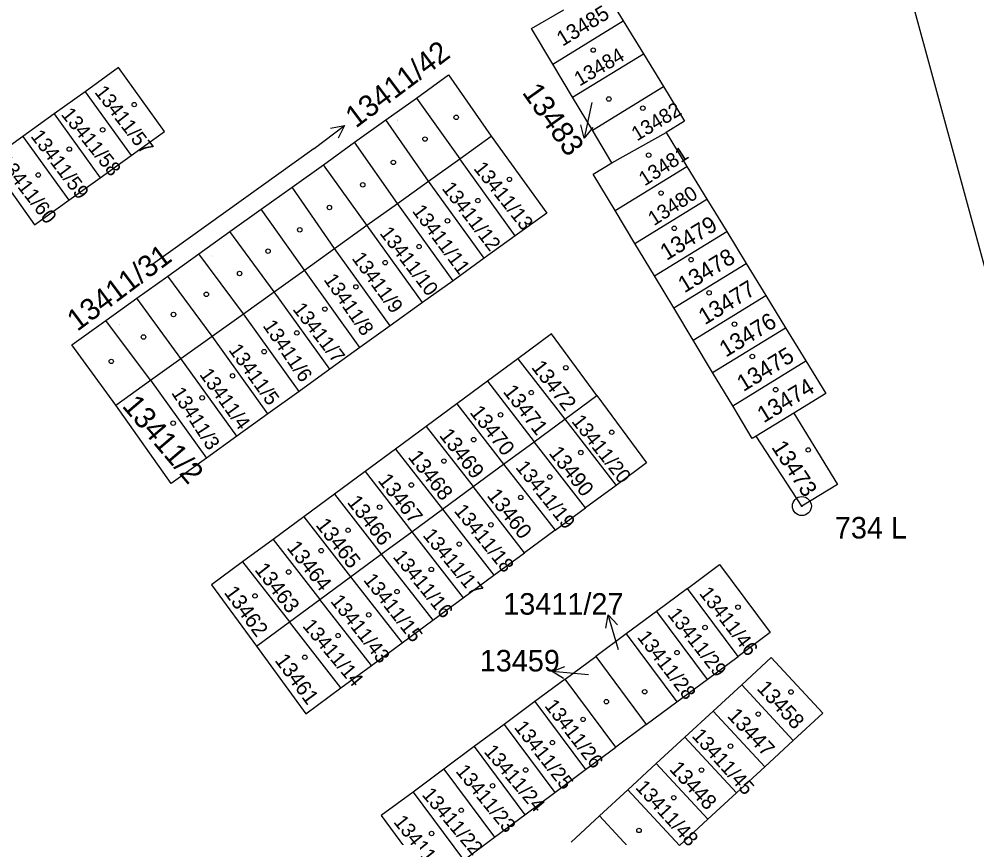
# Model space of a CAD drawing. Extents: x -822293 to -820259, y -1071573 to -1068794.
# Drawn here: x -820673 to -820597.4, y -1071103.6 to -1071039 of the extents above; entities that cross this region are included whole.
import ezdxf

# ---------------------------------------------------------------- set-up
doc = ezdxf.new("R2010")
doc.units = 0
for name, color, linetype in [('Vrstva 1', 7, 'Continuous'), ('Vrstva 16', 7, 'Continuous'), ('Vrstva 17', 7, 'Continuous'), ('Vrstva 19', 7, 'Continuous'), ('Vrstva 2', 7, 'Continuous'), ('Vrstva 24', 7, 'Continuous'), ('Vrstva 25', 7, 'Continuous')]:
    doc.layers.add(name, color=color, linetype=linetype)

msp = doc.modelspace()

# ---------------------------------------------------------------- linework, layer by layer
at = {"layer": 'Vrstva 1'}
msp.add_line((-820596.7, -1071059), (-820638.53, -1070906.11), dxfattribs=at)
at = {"layer": 'Vrstva 16'}
for p, q in [((-820627.8, -1071045.6), (-820628.42, -1071048.43)), ((-820649.71, -1071049.23), (-820647.314, -1071047.424)), ((-820649.71, -1071049.23), (-820662.44, -1071058.37)), ((-820625.7, -1071088.8), (-820626.52, -1071086.02)), ((-820628.07, -1071090.76), (-820630.95, -1071090.5))]:
    msp.add_line(p, q, dxfattribs=at)
for points in [[(-820648.414, -1071047.627), (-820647.314, -1071047.424), (-820647.812, -1071048.425)], [(-820627.742, -1071047.59), (-820628.42, -1071048.43), (-820628.685, -1071047.383)], [(-820626.71, -1071087.083), (-820626.52, -1071086.02), (-820625.783, -1071086.81)], [(-820630.033, -1071091.067), (-820630.95, -1071090.5), (-820629.947, -1071090.107)]]:
    msp.add_lwpolyline(points, dxfattribs=at)
at = {"layer": 'Vrstva 2'}
for p, q in [((-820626.88, -1071036.63), (-820625.33, -1071039.17)), ((-820632.58, -1071039.77), (-820630.01, -1071038.31)), ((-820630.9, -1071042.58), (-820632.58, -1071039.77)), ((-820630.9, -1071042.58), (-820625.33, -1071039.17)), ((-820625.33, -1071039.17), (-820623.74, -1071041.77)), ((-820629.33, -1071045.19), (-820623.74, -1071041.77)), ((-820623.74, -1071041.77), (-820622.15, -1071044.36)), ((-820665.15, -1071042.86), (-820667.79, -1071044.76)), ((-820661.52, -1071047.91), (-820665.15, -1071042.86)), ((-820629.33, -1071045.19), (-820630.9, -1071042.58)), ((-820641.65, -1071045.26), (-820639.12, -1071043.44)), ((-820639.12, -1071043.44), (-820635.75, -1071048.27)), ((-820627.77, -1071047.8), (-820622.15, -1071044.36)), ((-820622.15, -1071044.36), (-820620.49, -1071047.08)), ((-820667.79, -1071044.76), (-820670.23, -1071046.52)), ((-820667.79, -1071044.76), (-820664.16, -1071049.8)), ((-820644.06, -1071046.98), (-820641.65, -1071045.26)), ((-820641.65, -1071045.26), (-820638.22, -1071050.05)), ((-820627.77, -1071047.8), (-820629.33, -1071045.19)), ((-820670.23, -1071046.52), (-820672.7, -1071048.29)), ((-820670.23, -1071046.52), (-820666.6, -1071051.55)), ((-820646.53, -1071048.75), (-820644.06, -1071046.98)), ((-820640.69, -1071051.81), (-820644.06, -1071046.98)), ((-820620.49, -1071047.08), (-820621.95, -1071047.97)), ((-820664.16, -1071049.8), (-820661.52, -1071047.91)), ((-820626.23, -1071050.37), (-820627.77, -1071047.8)), ((-820626.23, -1071050.37), (-820621.95, -1071047.97)), ((-820621.95, -1071047.97), (-820620.31, -1071050.66)), ((-820672.7, -1071048.29), (-820675.36, -1071050.21)), ((-820672.7, -1071048.29), (-820669.07, -1071053.32)), ((-820648.99, -1071050.52), (-820646.53, -1071048.75)), ((-820643.15, -1071053.58), (-820646.53, -1071048.75)), ((-820638.22, -1071050.05), (-820635.75, -1071048.27)), ((-820635.75, -1071048.27), (-820631.36, -1071054.34)), ((-820675.36, -1071050.21), (-820671.77, -1071055.26)), ((-820666.6, -1071051.55), (-820664.16, -1071049.8)), ((-820640.69, -1071051.81), (-820638.22, -1071050.05)), ((-820633.85, -1071056.13), (-820638.22, -1071050.05)), ((-820627.7, -1071051.26), (-820626.23, -1071050.37)), ((-820651.45, -1071052.28), (-820648.99, -1071050.52)), ((-820645.55, -1071055.3), (-820648.99, -1071050.52)), ((-820625.97, -1071054.13), (-820620.31, -1071050.66)), ((-820620.31, -1071050.66), (-820618.73, -1071053.25)), ((-820669.07, -1071053.32), (-820666.6, -1071051.55)), ((-820643.15, -1071053.58), (-820640.69, -1071051.81)), ((-820636.31, -1071057.9), (-820640.69, -1071051.81)), ((-820625.97, -1071054.13), (-820627.7, -1071051.26)), ((-820653.9, -1071054.04), (-820651.45, -1071052.28)), ((-820648.11, -1071057.12), (-820651.45, -1071052.28)), ((-820671.77, -1071055.26), (-820669.07, -1071053.32)), ((-820624.41, -1071056.73), (-820618.73, -1071053.25)), ((-820618.73, -1071053.25), (-820617.17, -1071055.79)), ((-820656.36, -1071055.8), (-820653.9, -1071054.04)), ((-820650.49, -1071058.83), (-820653.9, -1071054.04)), ((-820645.55, -1071055.3), (-820643.15, -1071053.58)), ((-820638.76, -1071059.67), (-820643.15, -1071053.58)), ((-820624.41, -1071056.73), (-820625.97, -1071054.13)), ((-820631.36, -1071054.34), (-820633.85, -1071056.13)), ((-820648.11, -1071057.12), (-820645.55, -1071055.3)), ((-820641.16, -1071061.39), (-820645.55, -1071055.3)), ((-820658.82, -1071057.56), (-820656.36, -1071055.8)), ((-820652.87, -1071060.54), (-820656.36, -1071055.8)), ((-820633.85, -1071056.13), (-820636.31, -1071057.9)), ((-820622.87, -1071059.28), (-820617.17, -1071055.79)), ((-820617.17, -1071055.79), (-820615.63, -1071058.31)), ((-820650.49, -1071058.83), (-820648.11, -1071057.12)), ((-820643.71, -1071063.22), (-820648.11, -1071057.12)), ((-820622.87, -1071059.28), (-820624.41, -1071056.73)), ((-820661.27, -1071059.32), (-820658.82, -1071057.56)), ((-820655.3, -1071062.28), (-820658.82, -1071057.56)), ((-820636.31, -1071057.9), (-820638.76, -1071059.67)), ((-820621.35, -1071061.81), (-820615.63, -1071058.31)), ((-820615.63, -1071058.31), (-820614.08, -1071060.84)), ((-820663.71, -1071061.06), (-820661.27, -1071059.32)), ((-820657.77, -1071064.05), (-820661.27, -1071059.32)), ((-820652.87, -1071060.54), (-820650.49, -1071058.83)), ((-820646.1, -1071064.94), (-820650.49, -1071058.83)), ((-820621.35, -1071061.81), (-820622.87, -1071059.28)), ((-820638.76, -1071059.67), (-820641.16, -1071061.39)), ((-820655.3, -1071062.28), (-820652.87, -1071060.54)), ((-820648.49, -1071066.66), (-820652.87, -1071060.54)), ((-820619.82, -1071064.35), (-820614.08, -1071060.84)), ((-820614.08, -1071060.84), (-820612.53, -1071063.38)), ((-820666.16, -1071062.82), (-820663.71, -1071061.06)), ((-820660.23, -1071065.81), (-820663.71, -1071061.06)), ((-820641.16, -1071061.39), (-820643.71, -1071063.22)), ((-820657.77, -1071064.05), (-820655.3, -1071062.28)), ((-820650.9, -1071068.4), (-820655.3, -1071062.28)), ((-820619.82, -1071064.35), (-820621.35, -1071061.81)), ((-820668.84, -1071064.74), (-820666.16, -1071062.82)), ((-820662.63, -1071067.53), (-820666.16, -1071062.82)), ((-820643.71, -1071063.22), (-820646.1, -1071064.94)), ((-820660.23, -1071065.81), (-820657.77, -1071064.05)), ((-820653.36, -1071070.17), (-820657.77, -1071064.05)), ((-820630.98, -1071063.87), (-820633.64, -1071065.84)), ((-820627.41, -1071068.72), (-820630.98, -1071063.87)), ((-820618.29, -1071066.91), (-820612.53, -1071063.38)), ((-820612.53, -1071063.38), (-820610.92, -1071066)), ((-820665.36, -1071069.48), (-820668.84, -1071064.74)), ((-820618.29, -1071066.91), (-820619.82, -1071064.35)), ((-820646.1, -1071064.94), (-820648.49, -1071066.66)), ((-820662.63, -1071067.53), (-820660.23, -1071065.81)), ((-820655.82, -1071071.94), (-820660.23, -1071065.81)), ((-820633.64, -1071065.84), (-820636.05, -1071067.61)), ((-820633.64, -1071065.84), (-820629.95, -1071070.59)), ((-820616.7, -1071069.54), (-820610.92, -1071066)), ((-820610.92, -1071066), (-820609.35, -1071068.57)), ((-820648.49, -1071066.66), (-820650.9, -1071068.4)), ((-820616.7, -1071069.54), (-820618.29, -1071066.91)), ((-820665.36, -1071069.48), (-820662.63, -1071067.53)), ((-820662.63, -1071067.53), (-820658.21, -1071073.66)), ((-820636.05, -1071067.61), (-820638.46, -1071069.39)), ((-820636.05, -1071067.61), (-820632.36, -1071072.37)), ((-820650.9, -1071068.4), (-820653.36, -1071070.17)), ((-820609.35, -1071068.57), (-820611.88, -1071070.12)), ((-820629.95, -1071070.59), (-820627.41, -1071068.72)), ((-820627.41, -1071068.72), (-820623.49, -1071074.05)), ((-820660.99, -1071075.66), (-820665.36, -1071069.48)), ((-820638.46, -1071069.39), (-820640.88, -1071071.17)), ((-820638.46, -1071069.39), (-820634.77, -1071074.14)), ((-820615.15, -1071072.12), (-820616.7, -1071069.54)), ((-820653.36, -1071070.17), (-820655.82, -1071071.94)), ((-820632.36, -1071072.37), (-820629.95, -1071070.59)), ((-820629.95, -1071070.59), (-820625.89, -1071075.82)), ((-820611.88, -1071070.12), (-820614.84, -1071071.94)), ((-820611.88, -1071070.12), (-820608.44, -1071075.74)), ((-820640.88, -1071071.17), (-820643.29, -1071072.95)), ((-820640.88, -1071071.17), (-820637.18, -1071075.92)), ((-820655.82, -1071071.94), (-820658.21, -1071073.66)), ((-820634.77, -1071074.14), (-820632.36, -1071072.37)), ((-820628.3, -1071077.59), (-820632.36, -1071072.37)), ((-820614.84, -1071071.94), (-820615.15, -1071072.12)), ((-820611.24, -1071077.45), (-820614.84, -1071071.94)), ((-820643.29, -1071072.95), (-820645.7, -1071074.73)), ((-820643.29, -1071072.95), (-820639.59, -1071077.7)), ((-820658.21, -1071073.66), (-820660.99, -1071075.66)), ((-820637.18, -1071075.92), (-820634.77, -1071074.14)), ((-820634.77, -1071074.14), (-820630.7, -1071079.36)), ((-820623.49, -1071074.05), (-820625.89, -1071075.82)), ((-820645.7, -1071074.73), (-820648.12, -1071076.51)), ((-820645.7, -1071074.73), (-820642.02, -1071079.48)), ((-820639.59, -1071077.7), (-820637.18, -1071075.92)), ((-820633.11, -1071081.13), (-820637.18, -1071075.92)), ((-820625.89, -1071075.82), (-820628.3, -1071077.59)), ((-820608.44, -1071075.74), (-820611.24, -1071077.45)), ((-820648.12, -1071076.51), (-820650.53, -1071078.3)), ((-820648.12, -1071076.51), (-820644.42, -1071081.25)), ((-820630.7, -1071079.36), (-820628.3, -1071077.59)), ((-820650.53, -1071078.3), (-820652.95, -1071080.08)), ((-820650.53, -1071078.3), (-820646.84, -1071083.03)), ((-820642.02, -1071079.48), (-820639.59, -1071077.7)), ((-820639.59, -1071077.7), (-820635.53, -1071082.91)), ((-820644.42, -1071081.25), (-820642.02, -1071079.48)), ((-820642.02, -1071079.48), (-820637.96, -1071084.7)), ((-820630.7, -1071079.36), (-820633.11, -1071081.13)), ((-820652.95, -1071080.08), (-820655.36, -1071081.86)), ((-820652.95, -1071080.08), (-820649.26, -1071084.81)), ((-820646.84, -1071083.03), (-820644.42, -1071081.25)), ((-820644.42, -1071081.25), (-820640.35, -1071086.46)), ((-820635.53, -1071082.91), (-820633.11, -1071081.13)), ((-820655.36, -1071081.86), (-820657.82, -1071083.67)), ((-820655.36, -1071081.86), (-820651.67, -1071086.59)), ((-820620.27, -1071083.95), (-820617.73, -1071082.07)), ((-820617.73, -1071082.07), (-820613.74, -1071087.42)), ((-820637.96, -1071084.7), (-820635.53, -1071082.91)), ((-820657.82, -1071083.67), (-820654.27, -1071088.51)), ((-820649.26, -1071084.81), (-820646.84, -1071083.03)), ((-820646.84, -1071083.03), (-820642.78, -1071088.25)), ((-820620.27, -1071083.95), (-820622.71, -1071085.76)), ((-820616.28, -1071089.31), (-820620.27, -1071083.95)), ((-820651.67, -1071086.59), (-820649.26, -1071084.81)), ((-820645.19, -1071090.02), (-820649.26, -1071084.81)), ((-820640.35, -1071086.46), (-820637.96, -1071084.7)), ((-820622.71, -1071085.76), (-820625.09, -1071087.53)), ((-820622.71, -1071085.76), (-820618.72, -1071091.13)), ((-820654.27, -1071088.51), (-820651.67, -1071086.59)), ((-820647.61, -1071091.8), (-820651.67, -1071086.59)), ((-820642.78, -1071088.25), (-820640.35, -1071086.46)), ((-820613.74, -1071087.42), (-820616.28, -1071089.31)), ((-820625.09, -1071087.53), (-820627.5, -1071089.32)), ((-820625.09, -1071087.53), (-820621.11, -1071092.9)), ((-820654.27, -1071088.51), (-820650.36, -1071093.83)), ((-820645.19, -1071090.02), (-820642.78, -1071088.25)), ((-820629.91, -1071091.1), (-820627.5, -1071089.32)), ((-820627.5, -1071089.32), (-820623.52, -1071094.68)), ((-820618.72, -1071091.13), (-820616.28, -1071089.31)), ((-820615.99, -1071091.55), (-820613.67, -1071089.41)), ((-820613.67, -1071089.41), (-820609.6, -1071093.8)), ((-820647.61, -1071091.8), (-820645.19, -1071090.02)), ((-820629.91, -1071091.1), (-820632.3, -1071092.87)), ((-820625.93, -1071096.47), (-820629.91, -1071091.1)), ((-820621.11, -1071092.9), (-820618.72, -1071091.13)), ((-820650.36, -1071093.83), (-820647.61, -1071091.8)), ((-820618.24, -1071093.62), (-820615.99, -1071091.55)), ((-820615.99, -1071091.55), (-820611.92, -1071095.94)), ((-820632.3, -1071092.87), (-820634.72, -1071094.67)), ((-820632.3, -1071092.87), (-820628.31, -1071098.24)), ((-820623.52, -1071094.68), (-820621.11, -1071092.9)), ((-820620.47, -1071095.69), (-820618.24, -1071093.62)), ((-820614.17, -1071098.01), (-820618.24, -1071093.62)), ((-820609.6, -1071093.8), (-820611.92, -1071095.94)), ((-820634.72, -1071094.67), (-820637.09, -1071096.43)), ((-820634.72, -1071094.67), (-820630.73, -1071100.04)), ((-820623.52, -1071094.68), (-820625.93, -1071096.47)), ((-820622.74, -1071097.77), (-820620.47, -1071095.69)), ((-820620.47, -1071095.69), (-820616.4, -1071100.07)), ((-820637.09, -1071096.43), (-820639.49, -1071098.21)), ((-820637.09, -1071096.43), (-820633.1, -1071101.8)), ((-820628.31, -1071098.24), (-820625.93, -1071096.47)), ((-820611.92, -1071095.94), (-820614.17, -1071098.01)), ((-820624.97, -1071099.83), (-820622.74, -1071097.77)), ((-820618.67, -1071102.16), (-820622.74, -1071097.77)), ((-820616.4, -1071100.07), (-820614.17, -1071098.01)), ((-820639.49, -1071098.21), (-820641.91, -1071100.01)), ((-820639.49, -1071098.21), (-820635.49, -1071103.58)), ((-820630.73, -1071100.04), (-820628.31, -1071098.24)), ((-820641.91, -1071100.01), (-820644.43, -1071101.87)), ((-820641.91, -1071100.01), (-820637.92, -1071105.38)), ((-820633.1, -1071101.8), (-820630.73, -1071100.04)), ((-820627.21, -1071101.9), (-820624.97, -1071099.83)), ((-820624.97, -1071099.83), (-820620.9, -1071104.22)), ((-820616.4, -1071100.07), (-820618.67, -1071102.16)), ((-820635.49, -1071103.58), (-820633.1, -1071101.8)), ((-820644.43, -1071101.87), (-820640.43, -1071107.25)), ((-820629.45, -1071103.96), (-820627.21, -1071101.9)), ((-820623.14, -1071106.28), (-820627.21, -1071101.9)), ((-820620.9, -1071104.22), (-820618.67, -1071102.16)), ((-820637.92, -1071105.38), (-820635.49, -1071103.58))]:
    msp.add_line(p, q, dxfattribs=at)
at = {"layer": 'Vrstva 24'}
for radius in [0.75, 0.0327]:
    msp.add_circle((-820611.24, -1071077.45), radius, dxfattribs=at)
at = {"layer": 'Vrstva 25'}
for centre in [(-820627.7, -1071041.48), (-820626.47, -1071045.34), (-820663.91, -1071045.78), (-820623.79, -1071046.06), (-820638.51, -1071046.78), (-820666.4, -1071047.77), (-820640.97, -1071048.5), (-820669.03, -1071049.29), (-820623.33, -1071049.77), (-820643.47, -1071050.34), (-820671.48, -1071051.33), (-820645.88, -1071052.11), (-820634.31, -1071051.68), (-820622.35, -1071052.76), (-820636.8, -1071053.35), (-820648.51, -1071053.9), (-820639.2, -1071054.95), (-820650.85, -1071055.66), (-820621.31, -1071055.54), (-820653.35, -1071057.34), (-820641.44, -1071056.98), (-820619.98, -1071058.01), (-820644.11, -1071058.25), (-820655.6, -1071059.1), (-820646.42, -1071060.16), (-820658.22, -1071060.75), (-820618.56, -1071060.63), (-820648.87, -1071061.91), (-820660.81, -1071062.34), (-820616.56, -1071063.1), (-820663.18, -1071064.11), (-820651.08, -1071063.79), (-820653.66, -1071065.27), (-820615.15, -1071065.65), (-820665.72, -1071066.04), (-820656.15, -1071067.18), (-820629.86, -1071066.54), (-820632.59, -1071068.5), (-820613.31, -1071068.27), (-820658.55, -1071068.91), (-820635.01, -1071070.25), (-820660.84, -1071070.91), (-820626.24, -1071071.63), (-820637.13, -1071072.21), (-820628.68, -1071073.23), (-820610.74, -1071073.02), (-820639.48, -1071073.9), (-820631.13, -1071075.16), (-820642.05, -1071075.79), (-820633.42, -1071076.77), (-820644.55, -1071077.54), (-820635.77, -1071078.93), (-820647.04, -1071079.36), (-820638.27, -1071080.45), (-820649.16, -1071080.97), (-820651.73, -1071082.65), (-820640.47, -1071082.45), (-820654.38, -1071084.54), (-820643.18, -1071084.2), (-820645.41, -1071086.03), (-820616.28, -1071085.43), (-820618.88, -1071087.03), (-820647.83, -1071087.67), (-820621.09, -1071089.01), (-820650.45, -1071089.38), (-820623.64, -1071092.1), (-820612.1, -1071092.12), (-820626.66, -1071092.88), (-820628.5, -1071094.28), (-820614.68, -1071093.86), (-820630.92, -1071096.11), (-820616.87, -1071096.39), (-820633.03, -1071098.27), (-820619.16, -1071098.28), (-820635.64, -1071099.52), (-820621.35, -1071100.46), (-820638.11, -1071101.45), (-820640.45, -1071103.28), (-820624.09, -1071103.04)]:
    msp.add_circle(centre, 0.175, dxfattribs=at)

# ---------------------------------------------------------------- texts
at = {"layer": 'Vrstva 16'}
for s, rotation, p in [('13411/42', 36.98052, (-820646.43, -1071047.68)), ('13483', 305.33899, (-820633.36, -1071044.83)), ('13411/31', 36.81131, (-820668.4, -1071063.72))]:
    msp.add_text(s, height=1.7, rotation=rotation, dxfattribs=at).set_placement(p)
for s, p in [('13411/27', (-820634.799, -1071086.02)), ('13459', (-820636.654, -1071090.5))]:
    msp.add_text(s, height=1.7, dxfattribs=at).set_placement(p)
at = {"layer": 'Vrstva 17'}
msp.add_text('734 L', height=1.7, dxfattribs=at).set_placement((-820608.64, -1071080.01))
at = {"layer": 'Vrstva 19'}
for s, height, rotation, p in [('13485', 1.2, 31.46364, (-820630.123, -1071041.22)), ('13484', 1.139, 30.43582, (-820628.78, -1071044.36)), ('13411/57', 1.139, 307.771, (-820667.09, -1071044.81)), ('13411/42', 0.011, 307.64977, (-820640.88, -1071045.38)), ('13482', 1.139, 31.2184, (-820624.25, -1071048.69)), ('13411/58', 1.139, 308.71751, (-820669.73, -1071046.57)), ('13411/41', 0.0212, 306.35834, (-820643.18, -1071046.98)), ('13411/59', 1.139, 307.01332, (-820672.13, -1071048.28)), ('13411/40', 0.023, 306.54316, (-820645.52, -1071048.83)), ('13481', 1.139, 32.79088, (-820623.64, -1071052.24)), ('13411/60', 1.139, 307.66013, (-820674.72, -1071050.26)), ('13411/13', 1.139, 308.50688, (-820637.19, -1071050.83)), ('13411/39', 0.0146, 305.93281, (-820648.18, -1071050.59)), ('13411/12', 1.139, 307.50414, (-820639.69, -1071052.4)), ('13411/38', 0.0101, 305.11201, (-820650.52, -1071052.5)), ('13480', 1.139, 32.94921, (-820622.91, -1071055.38)), ('13411/37', 0.0119, 304.84682, (-820653.06, -1071054.18)), ('13411/11', 1.139, 306.54316, (-820642.03, -1071054.18)), ('13479', 1.3, 31.46418, (-820621.915, -1071058.118)), ('13411/10', 1.139, 307.35719, (-820644.6, -1071055.93)), ('13411/36', 0.00812, 305.19892, (-820655.36, -1071055.91)), ('13478', 1.3, 31.46337, (-820620.507, -1071060.675)), ('13411/35', 0.0346, 308.94666, (-820657.86, -1071057.67)), ('13411/9', 1.138, 306.16396, (-820646.79, -1071057.91)), ('13411/34', 0.023, 306.26946, (-820660.52, -1071059.39)), ('13411/8', 1.138, 304.6308, (-820649, -1071059.59)), ('13477', 1.3, 31.46364, (-820618.896, -1071063.196)), ('13411/33', 0.0063, 307.31063, (-820662.81, -1071061.32)), ('13411/7', 1.138, 307.65353, (-820651.46, -1071061.93)), ('13476', 1.3, 31.46382, (-820617.245, -1071065.748)), ('13411/32', 0.0302, 308.75615, (-820665.15, -1071063.04)), ('13411/6', 1.138, 304.08062, (-820653.81, -1071063.22)), ('13411/5', 1.138, 305.63513, (-820656.51, -1071065.14)), ('13411/31', 0.0181, 309.24707, (-820667.98, -1071064.93)), ('13475', 1.3, 31.4631, (-820615.856, -1071068.461)), ('13472', 1.2, 307.83915, (-820632.635, -1071066.514)), ('13411/4', 1.138, 305.66651, (-820658.81, -1071067.07)), ('13474', 1.3, 31.54689, (-820614.253, -1071070.93)), ('13411/3', 1.138, 302.79349, (-820661.02, -1071068.51)), ('13471', 1.2, 307.72917, (-820634.866, -1071068.437)), ('13411/2', 1.7, 310.38365, (-820664.93, -1071069.58)), ('13470', 1.2, 307.88469, (-820637.493, -1071070.072)), ('13411/20', 1.139, 308.22129, (-820629.46, -1071070.78)), ('13469', 1.2, 307.93158, (-820639.898, -1071071.889)), ('13473', 1.3, 303.14538, (-820613.685, -1071072.803)), ('13468', 1.2, 307.93185, (-820642.366, -1071073.598)), ('13490', 1.2, 307.94022, (-820631.256, -1071073.288)), ('13411/19', 1.139, 308.56434, (-820633.88, -1071074.41)), ('13467', 1.2, 307.84185, (-820644.743, -1071075.443)), ('13460', 1.2, 307.93104, (-820636.136, -1071076.638)), ('13466', 1.2, 307.97703, (-820647.169, -1071077.159)), ('13411/18', 1.139, 308.82369, (-820638.73, -1071077.85)), ('13465', 1.2, 307.95885, (-820649.642, -1071078.961)), ('13411/17', 1.139, 309.36461, (-820641.2, -1071079.78)), ('13464', 1.2, 307.93347, (-820651.928, -1071080.749)), ('13411/16', 1.139, 309.06765, (-820643.56, -1071081.47)), ('13463', 1.2, 307.93428, (-820654.464, -1071082.485)), ('13411/15', 1.139, 308.11298, (-820645.88, -1071083.3)), ('13462', 1.2, 306.25578, (-820656.872, -1071084.282)), ('13411/46', 1.139, 307.52477, (-820619.39, -1071084.35)), ('13411/43', 1.139, 308.22309, (-820648.48, -1071084.97)), ('13411/29', 1.139, 307.92917, (-820621.89, -1071086.02)), ('13411/14', 1.139, 309.89306, (-820650.69, -1071086.93)), ('13411/28', 1.139, 307.51327, (-820624.28, -1071087.8)), ('13461', 1.2, 306.2565, (-820652.869, -1071089.629)), ('13458', 1.2, 312.8346, (-820614.855, -1071091.879)), ('13411/26', 1.139, 307.53696, (-820631.59, -1071093.22)), ('13447', 1.2, 312.83739, (-820617.187, -1071094.05)), ('13411/25', 1.139, 308.00518, (-820633.99, -1071094.92)), ('13411/45', 1.139, 311.86523, (-820619.98, -1071095.61)), ('13411/24', 1.139, 310.3141, (-820636.38, -1071096.85)), ('13411/23', 1.139, 309.08584, (-820638.6, -1071098.39)), ('13448', 1.2, 312.83712, (-820621.759, -1071098.246)), ('13411/48', 1.139, 312.30284, (-820624.43, -1071099.69)), ('13411/22', 1.139, 310.09763, (-820641.27, -1071100.24)), ('13411/21', 1.139, 308.60166, (-820643.51, -1071102.38))]:
    msp.add_text(s, height=height, rotation=rotation, dxfattribs=at).set_placement(p)
for s, p in [('13483', (-820627.8, -1071045.6)), ('13411/27', (-820625.7, -1071088.8)), ('13459', (-820628.07, -1071090.76))]:
    msp.add_text(s, height=0.005, dxfattribs=at).set_placement(p)

doc.saveas('drawing.dxf')
